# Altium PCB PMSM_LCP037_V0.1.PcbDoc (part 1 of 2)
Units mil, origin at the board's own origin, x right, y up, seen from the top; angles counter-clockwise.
Board outline 6102.36 x 5157.48 mil, 2 copper layers (Top Layer, Bottom Layer); 106 components, 56 nets, 276 pads, 861 vias.
Unrouted connection lines stored in the file: 2.
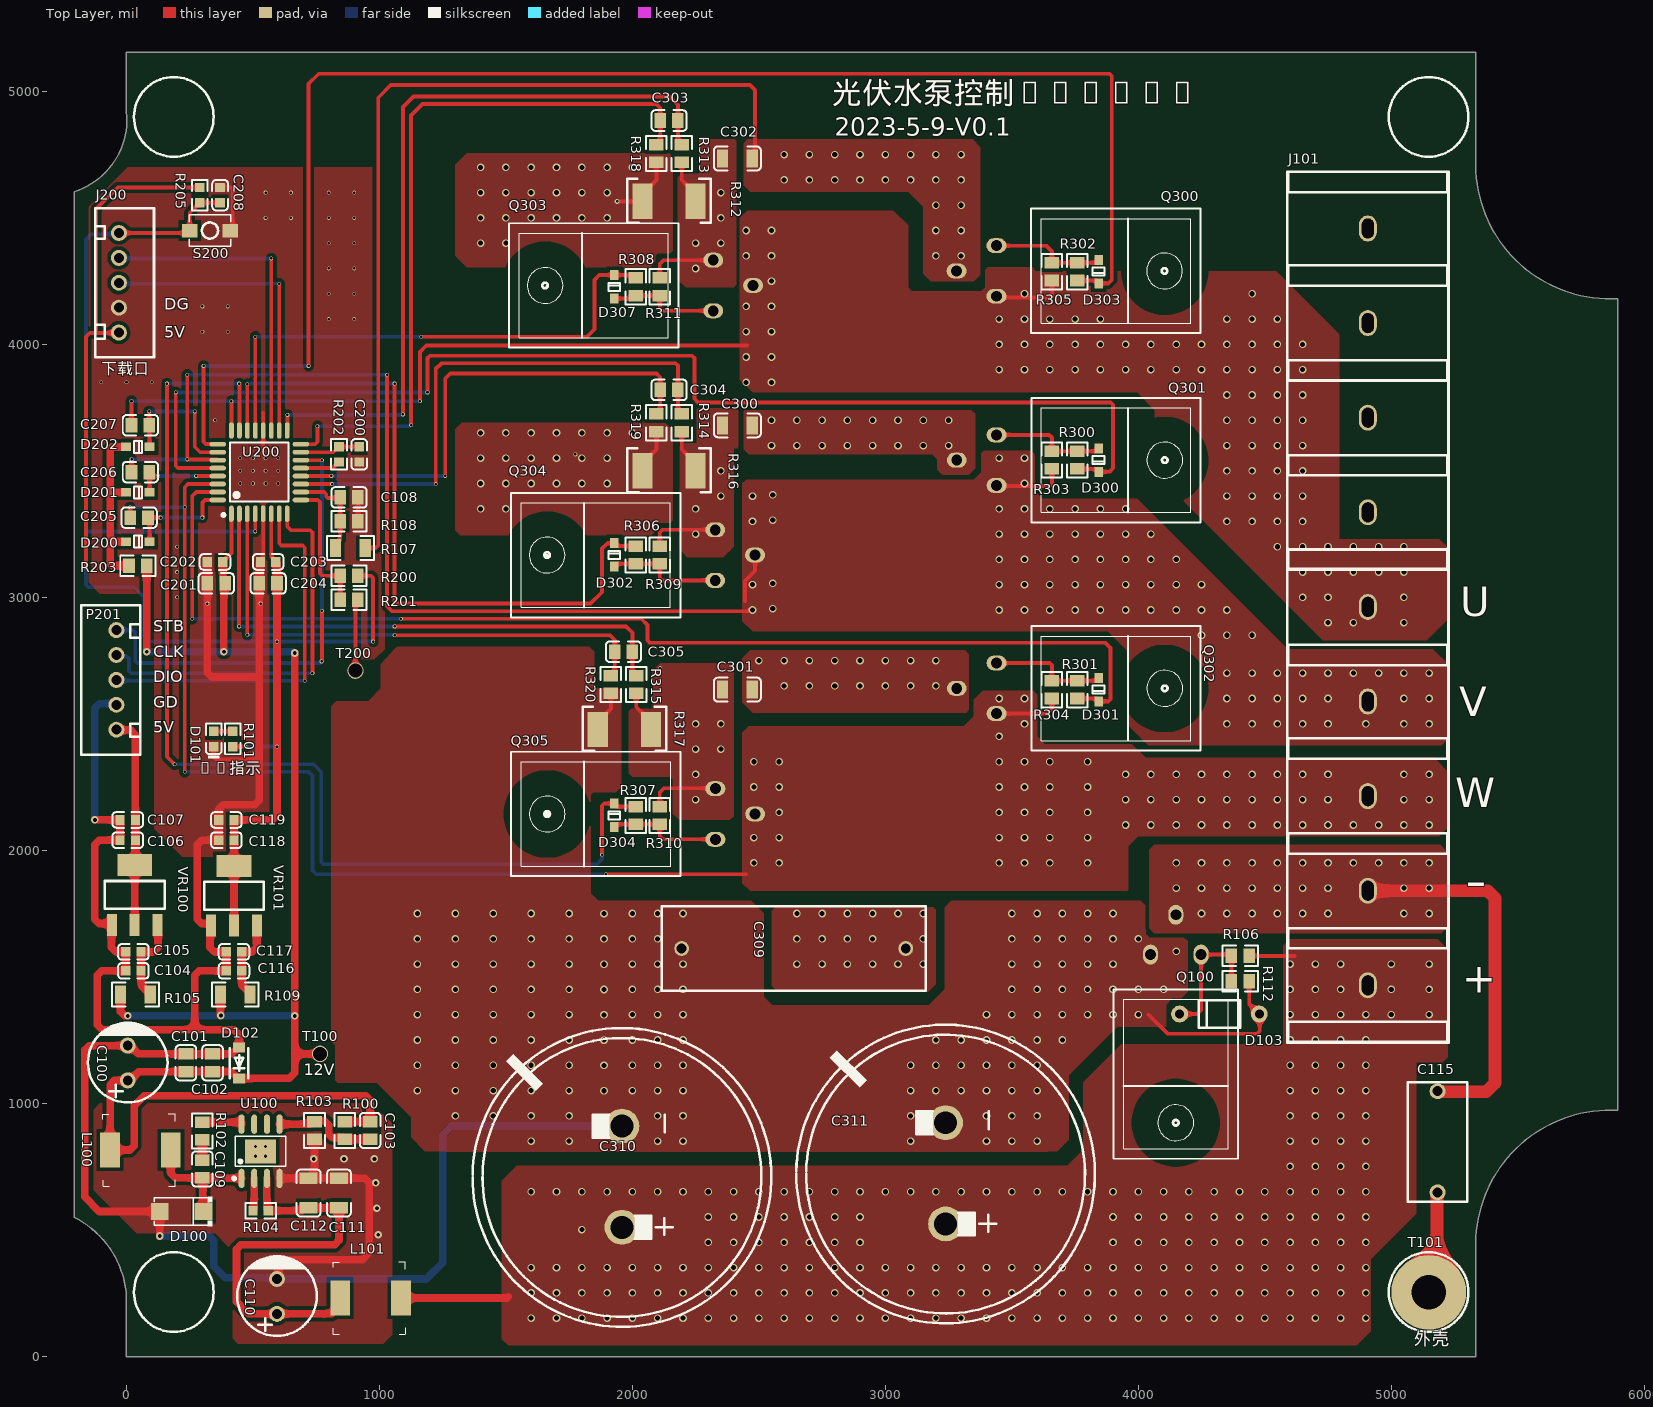
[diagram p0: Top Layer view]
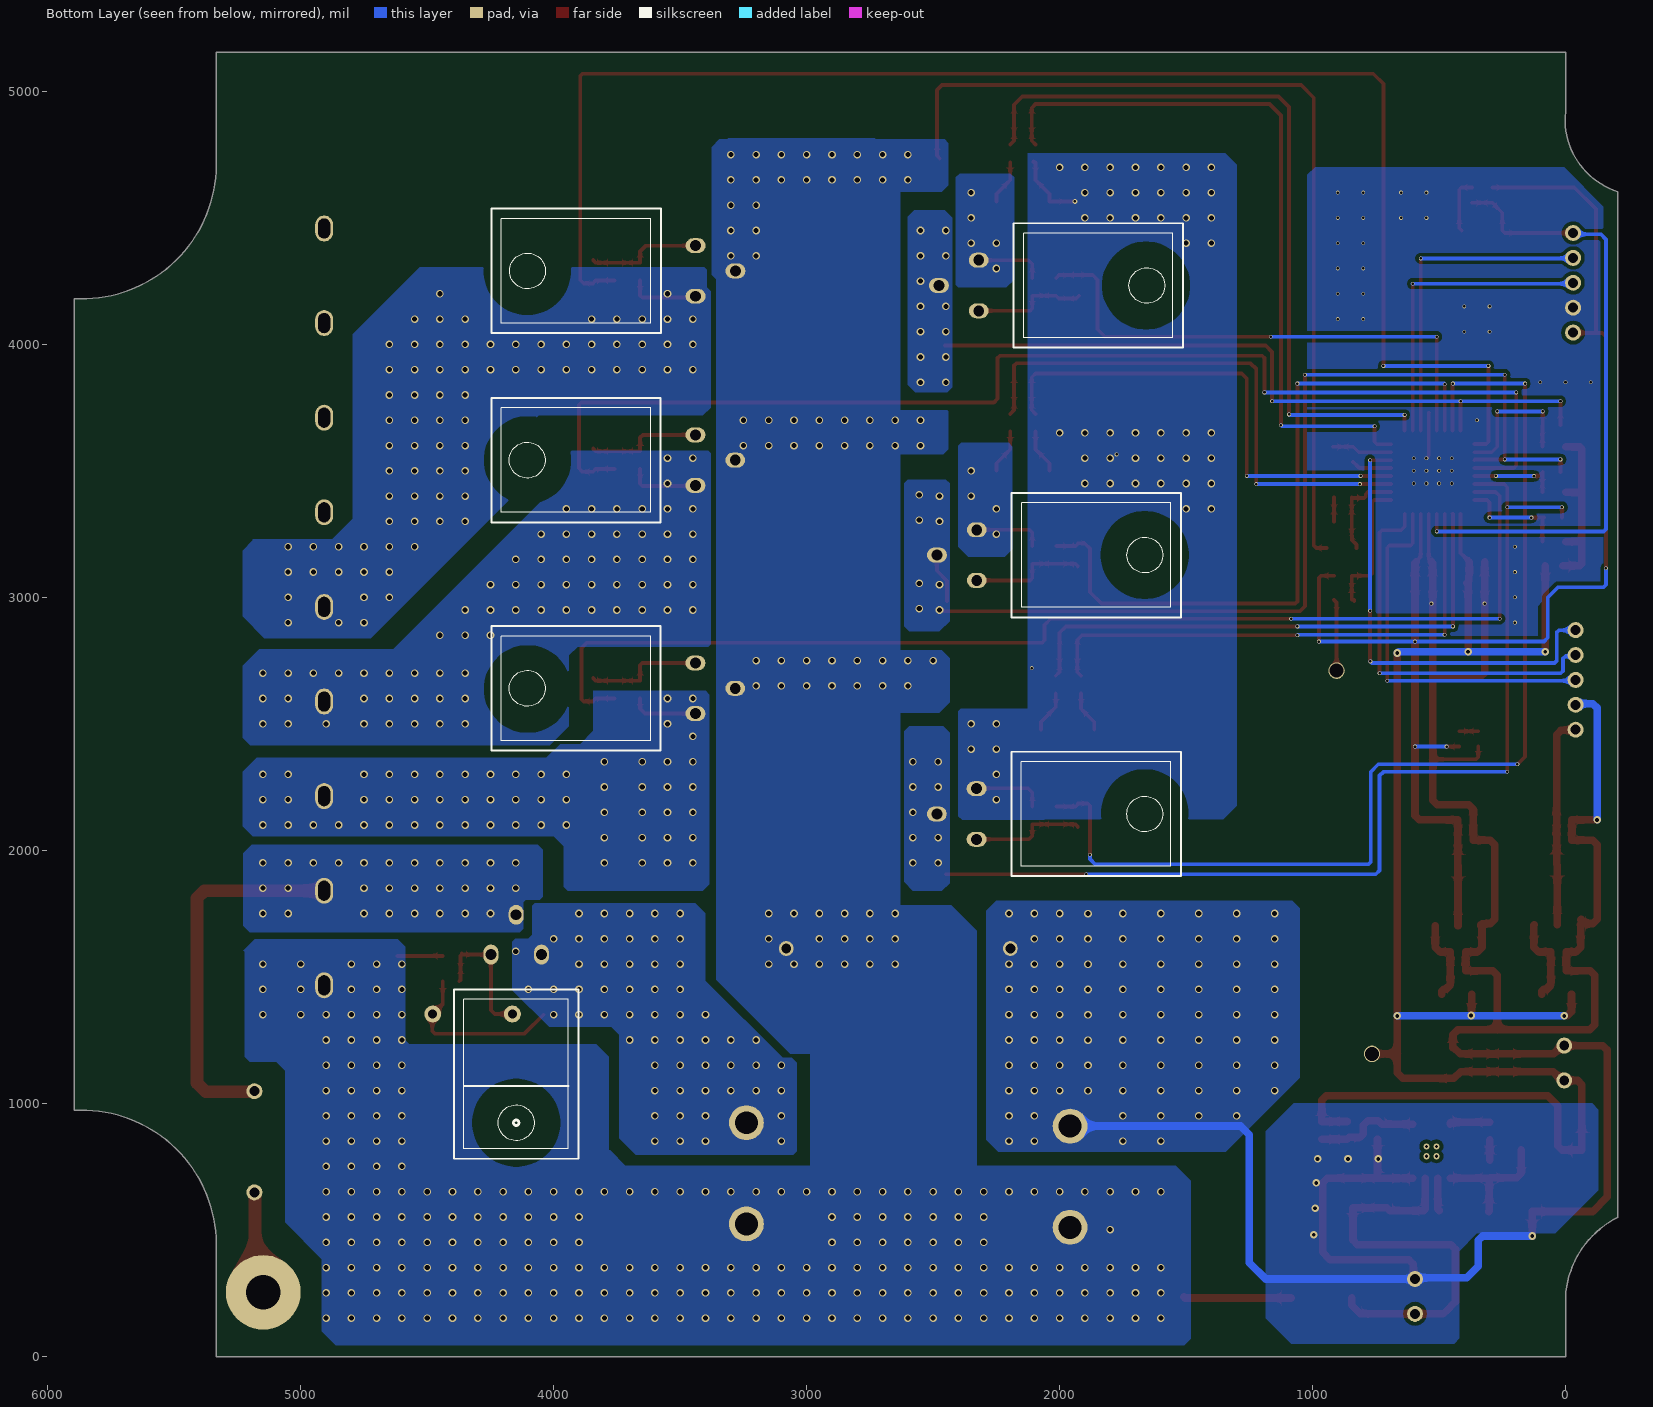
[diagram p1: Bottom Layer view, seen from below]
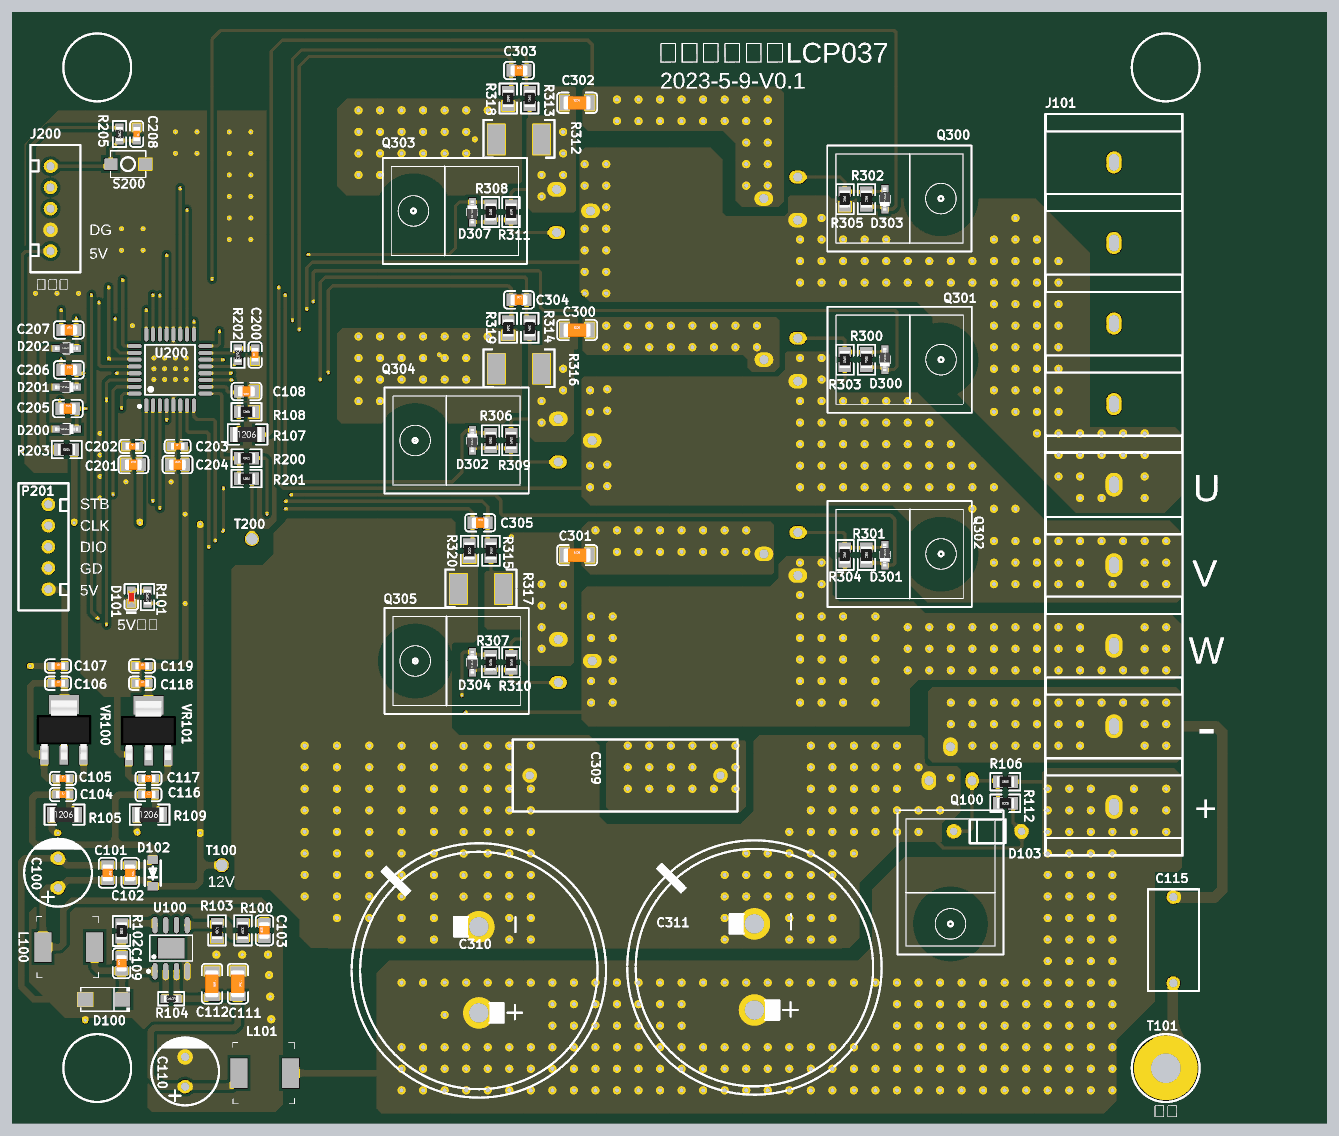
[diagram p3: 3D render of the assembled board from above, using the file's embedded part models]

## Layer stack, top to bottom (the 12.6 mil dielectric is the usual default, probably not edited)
Top Solder: solder mask 0.4, Solder Resist, Dk 3.5
Top Layer: signal copper 1.4
Dielectric 1: dielectric 12.6, FR-4, Dk 4.8
Bottom Layer: signal copper 1.4
Bottom Solder: solder mask 0.4, Solder Resist, Dk 3.5

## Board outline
0,-2.48 0,233.74 ccw(c-374.92,213) -206.69,548.7 -206.69,4603.82 ccw(c-297.17,4888.49) 0,4918.78 0,5155 5334.65,5155 5334.65,4682.56 ccw(c5866.14,4712.09) 5895.67,4180.59 5895.67,971.93 ccw(c5866.14,440.43) 5334.65,469.96 5334.65,-2.48

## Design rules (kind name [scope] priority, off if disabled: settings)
Clearance [All] p1: gap=10 ignorepadtopadclearanceinfootprint=FALSE
ComponentClearance [All] p1: gap=0 collisioncheckmode=3 verticalgap=0 showdistances=FALSE
HoleSize [All] p1: absolutevalues=TRUE maxlimit=500 minlimit=1 maxpercent=80.000 minpercent=20.000
HoleToHoleClearance [All] p1: gap=0 allowstackedmicrovias=TRUE
MinimumSolderMaskSliver [All] p1: minsoldermaskwidth=0
PlaneConnect [All] p1: planeconnectstyle=Direct reliefexpansion=20 reliefentries=4 reliefconductorwidth=10 reliefairgap=10
PolygonConnect [All] p1: connectstyle=Direct reliefconductorwidth=10 reliefentries=4 polygonreliefangle="90 Angle" airgapwidth=10
RoutingVias [All] p1: holewidth=10 width=13 viastyle="Through Hole" minholewidth=10 minwidth=13 maxholewidth=500 maxwidth=500
SilkToSilkClearance [All] p1: silktosilkclearance=0
SilkToSolderMaskClearance [IsPad] p1: minsilkscreentomaskgap=0 clearancetoexposedcopper=TRUE
SolderMaskExpansion [All] p1: expansion=4 istentingtop=FALSE
Width [All] p1: maxlimit=500 minlimit=6 preferedwidth=10
23 further rules are at their usual default settings.

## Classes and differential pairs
component class 03_Mos: C300 C301 C302 C303 C304 C305 C309 C310 C311 D300 D301 D302 D303 D304 D307 Q300 Q301 Q302 Q303 Q304 Q305 R300 R301 R302 R303 R304 R305 R306 R307 R308 R309 R310 R311 R312 R313 R314 R315 R316 R317 R318 R319 R320
component class 02_MCU: C200 C201 C202 C203 C204 C205 C206 C207 C208 D200 D201 D202 J200 P201 R200 R201 R202 R203 R205 S200 T200 U200
component class 01_Power: C100 C101 C102 C103 C104 C105 C106 C107 C108 C109 C110 C111 C112 C115 C116 C117 C118 C119 D100 D101 D102 D103 J101 L100 L101 Q100 R100 R101 R102 R103 R104 R105 R106 R107 R108 R109 R112 T100 T101 U100 VR100 VR101

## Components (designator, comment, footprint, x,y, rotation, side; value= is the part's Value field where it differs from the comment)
C100 "470uF/25V" 47UF/100V 5,1090 r90 top
C101 "22uF (226) 20% 25V" 0805_C 235,1160 r270 top
C102 "100nF(104) 10% 50V" 0805_C 340,1160 r270 top
C103 "47pF (470) 5% 50V" 0805_C 963.31,892.52 r90 top
C104 "100nF (104) 10% 50V" 0603_C 27.48,1523.31 r0 top
C105 "10uF (106) 10% 10V" 0603_C 27.48,1598.31 r0 top
C106 "100nF (104) 10% 50V" 0603_C 5,2040 r0 top
C107 "10uF (106) 10% 10V" 0603_C 5,2120 r0 top
C108 "100nF(104) 10% 50V" 0805_C 880,3395 r180 top
C109 "100nF(104) 10% 50V" 0805_C 300,740 r90 top
C110 "47uF/100V" 47UF/100V 595,167.2 r90 top
C111 "2.2uF (225) 10% 50V" 1206_C 840,645 r270 top
C112 "100nF (104) 10% 50V" 1206_C 720,645 r270 top
C115 "2.2nF (222) 10% 50V" "X1/Y1 500V" 5183.31,1047.52 r270 top
C116 "100nF (104) 10% 50V" 0603_C 425,1523.31 r0 top
C117 "10uF (106) 10% 10V" 0603_C 425,1598.31 r0 top
C118 "100nF (104) 10% 50V" 0603_C 395,2040 r0 top
C119 "10uF (106) 10% 10V" 0603_C 395,2120 r0 top
C200 "1uF (105) 10% 50V" 0603_C 920,3565 r90 top
C201 "10uF (106) 10% 25V" 0805_C 354.96,3055 r0 top
C202 "100nF (104) 10% 50V" 0603_C 350,3140 r0 top
C203 "100nF (104) 10% 50V" 0603_C 560,3140 r0 top
C204 "10uF (106) 10% 25V" 0805_C 560,3055 r0 top
C205 "10uF (106) 10% 25V" 0805_C 50,3315 r0 top
C206 "10uF (106) 10% 25V" 0805_C 54.88,3495 r0 top
C207 "10uF (106) 10% 25V" 0805_C 54.88,3680 r0 top
C208 "100nF (104) 10% 50V" 0603_C 370,4590 r270 top
C300 "100nF (104) 10% 100V" 1206_C 2415,3680 r0 top
C301 "100nF (104) 10% 100V" 1206_C 2415,2635 r0 top
C302 "100nF (104) 10% 100V" 1206_C 2415,4735 r0 top
C303 "100pF (101) 5% 50V" 0805_C 2145,4885 r0 top
C304 "100pF (101) 5% 50V" 0805_C 2145,3820 r0 top
C305 "100pF (101) 5% 50V" 0805_C 1965,2785 r0 top
C309 "X2 1UF/310V" "X2 1UF 310V" 2194.88,1611.69 r0 top
C310 "1000uF/250V" 1000uf/250V 1958.66,509.33 r90 top
C311 "1000uF/250V" 1000uf/250V 3238.19,522.72 r90 top
D100 "SS310" SS310 215,570 r180 top
D101 "绿灯 0603" 0603_LED_S1 345,2440 r90 top
D102 "SMF12A" "SMF12A - duplicate" 445,1097.95 r90 top
D103 "1N4746A" 1N4746A 4301.77,1252.64 r180 top
D200 "1N4148WS T4" SOD-323 45,3220 r180 top
D201 "1N4148WS T4" SOD-323 44.88,3415 r180 top
D202 "1N4148WS T4" SOD-323 44.88,3595 r180 top
D300 "1N4148WS T4" SOD-323 3843.31,3542.52 r90 top
D301 "1N4148WS T4" SOD-323 3843.31,2635 r90 top
D302 "1N4148WS T4" SOD-323 1928.31,3167.52 r270 top
D303 "1N4148WS T4" SOD-323 3843.31,4287.52 r90 top
D304 "1N4148WS T4" SOD-323 1928.31,2137.52 r270 top
D307 "1N4148WS T4" SOD-323 1928.31,4227.52 r270 top
J101 "CON9" "CON9 9.5mm" 4907.48,1466.02 r90 top locked
J200 "SWD-KF2510-5P" XH2.54-5P -30,4046.58 r90 top
L100 "47uH/0650" 0650_47UH 45,815 r180 top
L101 "47uH/0650" 0650_47UH 955,230 r180 top
P201 "Header 5" XH2.54-5P -40,2870.28 r270 top
Q100 "IRFB4127PBF" IRFB4127#1 4148.31,1745 r180 top locked
Q300 "IRFB4127PBF" IRFB4127#2 3439.02,4390.24 r270 top locked
Q301 "IRFB4127PBF" IRFB4127#2 3439.8,3642.2 r270 top locked
Q302 "IRFB4127PBF" IRFB4127#2 3439.8,2740.24 r270 top locked
Q303 "IRFB4127PBF" IRFB4127#2 2319.72,4132.76 r90 top locked
Q304 "IRFB4127PBF" IRFB4127#2 2327.6,3067.01 r90 top locked
Q305 "IRFB4127PBF" IRFB4127#2 2327.99,2043.39 r90 top locked
R100 "330KΩ (3303) ±1%" 0805_R 863.31,892.52 r90 top
R101 "10KΩ (1002) ±1%" 0603_R 420,2440 r270 top
R102 "22Ω (22R0) ±1%" 0805_R 300,890 r90 top
R103 "23.7KΩ" 0805_R 743.31,892.52 r90 top
R104 "30mΩ ±1%" 0603_R 530,575 r0 top
R105 "200Ω (2000) ±1%" 1206_R 35,1430 r0 top
R106 "20KΩ (2002) ±1%" 0805_R 4403.31,1582.52 r0 top
R107 "24KΩ (2402) ±1%" 1206_R 885,3195 r0 top
R108 "1KΩ (1001) ±1%" 0805_R 880,3300 r180 top
R109 "200Ω (2000) ±1%" 1206_R 430,1430 r0 top
R112 "10KΩ (1002) ±1%" 0805_R 4403.31,1482.52 r180 top
R200 "1KΩ (1001) ±1%" 0805_R 880,3085 r0 top
R201 "1KΩ (1001) ±1%" 0805_R 880,2990 r180 top
R202 "10KΩ (1002) ±1%" 0603_R 840,3565 r270 top
R203 "1KΩ (1001) ±1%" 0805_R 45,3125 r180 top
R205 "10KΩ (1002) ±1%" 0603_R 290,4590 r90 top
R300 "51Ω (51R0) ±1%" 0805_R 3758.31,3542.56 r90 top
R301 "51Ω (51R0) ±1%" 0805_R 3758.31,2635 r90 top
R302 "51Ω (51R0) ±1%" 0805_R 3758.31,4287.52 r90 top
R303 "100KΩ (1003) ±1%" 0805_R 3658.31,3542.52 r90 top
R304 "100KΩ (1003) ±1%" 0805_R 3658.31,2635 r90 top
R305 "100KΩ (1003) ±1%" 0805_R 3658.31,4287.52 r90 top
R306 "51Ω (51R0) ±1%" 0805_R 2013.31,3167.52 r270 top
R307 "51Ω (51R0) ±1%" 0805_R 2013.31,2137.52 r270 top
R308 "51Ω (51R0) ±1%" 0805_R 2013.31,4227.52 r270 top
R309 "100KΩ (1003) ±1%" 0805_R 2108.31,3167.52 r270 top
R310 "100KΩ (1003) ±1%" 0805_R 2108.31,2137.52 r270 top
R311 "100KΩ (1003) ±1%" 0805_R 2108.31,4227.52 r270 top
R312 "10mR 2512" R2512 2170,4525 r0 top
R313 "68Ω (68R0) ±1%" 0805_R 2195,4755 r270 top
R314 "68Ω (68R0) ±1%" 0805_R 2195,3690 r270 top
R315 "68Ω (68R0) ±1%" 0805_R 2015,2655 r270 top
R316 "10mR 2512" R2512 2170,3460 r0 top
R317 "10mR 2512" R2512 1993.31,2437.52 r0 top
R318 "68Ω (68R0) ±1%" 0805_R 2095,4755 r270 top
R319 "68Ω (68R0) ±1%" 0805_R 2095,3690 r270 top
R320 "68Ω (68R0) ±1%" 0805_R 1915,2655 r270 top
S200 "KEY" 按键3*4 249.76,4450 r0 top
T100 "Test" Testpoint 765,1195 r90 top
T101 "Test" 接地螺丝孔 5148.31,252.52 r0 top
T200 "Test" Testpoint 905,2710 r90 top
U100 "TX4139" ESOP8 455,702.89 r0 top
U200 "LCP037BK32ET8" LQFP32 425,3395 r270 top
VR100 "AMS1117-5.0" SOT-223 32.48,1823.31 r270 top
VR101 "AMS1117-5.0" SOT-223 425,1820 r270 top

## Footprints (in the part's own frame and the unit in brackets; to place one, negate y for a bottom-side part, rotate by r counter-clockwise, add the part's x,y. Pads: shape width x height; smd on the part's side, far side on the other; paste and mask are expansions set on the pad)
1N4746A [mm]
  round 1.7 hole 0.9 paste+0 mask+0.051: 1(-4.484,-2.537) 2(3.516,-2.537)
  silkscreen extent -2.58,-3.94 1.62,-1.14
47UF/100V [mm] "8*14"
  round 1.6 hole 1: 1(0,0) 2(3.5,0)
  silkscreen extent -2.21,-4 5.79,4
0603_C [mm]
  rect 0.93x0.98 smd: 1(-0.77,0) 2(0.77,0)
  silkscreen extent -1.53,-0.79 1.54,0.79, body extent -0.8,-0.4 0.8,0.4, height 0.3
0603_LED_S1 [mm]
  rect 0.93x0.98 smd: A(0.77,0) K(-0.77,0)
  silkscreen extent -1.98,-0.79 1.54,0.79, body extent -0.8,-0.4 0.8,0.4, height 0.6
0603_R [mm]
  rect 0.93x0.98 smd: 1(-0.77,0) 2(0.77,0)
  silkscreen extent -1.53,-0.79 1.54,0.79, body extent -0.85,-0.4 0.85,0.4, height 0.56
0650_47UH [mm]
  rect 2x3.5 smd: 1(-3.302,0) 2(2.794,0)
  silkscreen extent -3.76,-3.62 3.52,3.62
0805_C [mm]
  rect 1.16x1.47 smd: 1(-0.89,0) 2(0.89,0)
  silkscreen extent -1.77,-1.04 1.77,1.04, body extent -1,-0.62 1,0.63, height 0.77
0805_R [mm]
  rect 1.16x1.47 smd: 1(-0.89,0) 2(0.89,0)
  silkscreen extent -1.77,-1.04 1.77,1.03, body extent -1,-0.62 1,0.63, height 0.49
1000uf/250V [mm]
  round 3.5 hole 2.3: 1(0,0) 2(10.16,0)
  silkscreen extent -9.99,-15 20.01,15
1206_C [mm]
  rect 1.13x1.8 smd: 1(-1.49,0) 2(1.49,0)
  silkscreen extent -2.36,-1.2 2.35,1.2, body extent -1.6,-0.81 1.6,0.79, height 1
1206_R [mm]
  rect 1.13x1.8 smd: 1(-1.49,0) 2(1.49,0)
  silkscreen extent -2.36,-1.2 2.35,1.2, body extent -1.7,-0.86 1.65,0.87, height 0.85
"CON9 9.5mm" [mm]
  oval 2.6x1.8 hole 1.2 slot 2 at 0 deg: 1(0,0) 2(9.5,0) 3(19,0) 4(28.5,0) 5(38,0) 6(47.5,0) 7(57,0) 8(66.5,0) 9(76,0)
  silkscreen extent -5.75,-8.1 81.69,8.1
ESOP8 [mm]
  oval 0.602x1.941 smd: 1(0,0) 2(1.27,0) 3(2.54,0) 4(3.81,0) 5(3.81,5.441) 6(2.54,5.441) 7(1.27,5.441) 8(0,5.441)
  rect 3.098x2.41 smd: 9(1.905,2.72)
  silkscreen extent -0.9,-0.15 4.43,4.24
IRFB4127#1 [mm]
  oval 1.5x2 hole 1.1: 1(-2.54,4) 2(0,0) 3(2.54,4)
  silkscreen extent -6.25,7.5 6.25,24.5
IRFB4127#2 [mm] "TO-220AB"
  oval 1.5x2 hole 1.1: 1(0,0) 2(2.54,-4) 3(5.08,0)
  round 0 on Bottom Overlay: ""(2.54,16.885)
  silkscreen extent -3.71,3.5 8.79,20.5
LQFP32 [mm]
  oval 1.65x0.48 smd: 1(1.635,-0.26) 2(1.635,0.54) 3(1.635,1.34) 4(1.635,2.14) 5(1.635,2.94) 6(1.635,3.74) 7(1.635,4.54) 8(1.635,5.34) 17(-6.715,5.34) 18(-6.715,4.54) 19(-6.715,3.74) 20(-6.715,2.94) 21(-6.715,2.14) 22(-6.715,1.34) 23(-6.715,0.54) 24(-6.715,-0.26)
  oval 0.48x1.65 smd: 9(0.26,6.715) 10(-0.54,6.715) 11(-1.34,6.715) 12(-2.14,6.715) 13(-2.94,6.715) 14(-3.74,6.715) 15(-4.54,6.715) 16(-5.34,6.715) 25(-5.34,-1.635) 26(-4.54,-1.635) 27(-3.74,-1.635) 28(-2.94,-1.635) 29(-2.14,-1.635) 30(-1.34,-1.635) 31(-0.54,-1.635) 32(0.26,-1.635)
  silkscreen extent -5.49,-1.21 1.91,5.49
R2512 [mil]
  rect 80x140 smd: 1(-130,40) 2(80,40)
  silkscreen extent -190,-45 140,130
"SMF12A - duplicate" [mm] "SOD123F"
  rect 1x1.2 smd: 1(0,0) 2(3.1,0)
  silkscreen extent 0.03,-0.93 3.04,0.95
SOD-323 [mm]
  rect 1x0.83 smd: 1(1.18,0) 2(-1.18,0)
  silkscreen extent -0.4,-0.6 0.4,0.6, body extent -1.35,-0.62 1.35,0.63, height 1.1
SOT-223 [mm]
  rect 2.2x1 smd: 1(3,-2.3) 2(3,0) 3(3,2.3)
  rect 2.2x3.5 smd: 2(-3,0)
  silkscreen extent -1.4,-3 1.4,3, body extent -3.49,-3.24 3.49,3.24, height 1.64
SS310 [mm]
  rect 1.8x1.7 smd paste+0 mask+0.051: 1(-2.26,-0.047) 2(2.125,-0.047)
  silkscreen extent -3.17,-1.52 2.66,1.43
Testpoint [mil]
  round 65 hole 55: 1(0,0)
"X1/Y1 500V" [mm]
  round 1.6 hole 1: 1(0,0) 2(10.16,0)
  silkscreen extent -0.92,-3 11.08,3
"X2 1UF 310V" [mm]
  round 1.5 hole 1: 1(0,0) 2(22.5,0)
  silkscreen extent -2,-4.25 24.5,4.25
XH2.54-5P [mm]
  round 1.6 hole 1 paste+0 mask+0.05: 1(0,0) 2(2.5,0) 3(5,0) 4(7.5,0) 5(10,0)
  silkscreen extent -2.5,-3.53 12.5,2.38
按键3*4 [mm]
  rect 1.53x1.36 smd: 1(0,0) 2(4.07,0)
  silkscreen extent -0.04,-1.58 4.11,1.58
接地螺丝孔 [mm]
  round 7.5 hole 3.5: 6(0,0)

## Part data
C100 C110: library part CapSMT220u_16V
C101: library part "0805 22uF (226) 20% 25V", "贴片电容", Package=0805, SuppliersPartNumber=C45783
C102 C108 C109: library part "0805 100nF(104) 10% 50V", "贴片电容", Package=0805, SuppliersPartNumber=C49678
C103: library part "0805 47pF (470) 5% 50V", "贴片电容", Package=0805, SuppliersPartNumber=C14857
C104 C106 C116 C118 C202 C203 C208: library part "0603 100nF (104) 10% 50V", "贴片电容", Package=0603, SuppliersPartNumber=C14663
C105 C107 C117 C119: library part "0603 10uF (106) 10% 10V", "贴片电容", Package=0603, SuppliersPartNumber=C19702
C111: library part "1206 2.2uF (225) 10% 50V", "贴片电容", Package=1206, SuppliersPartNumber=C12656
C112 C300 C301 C302 C309: library part "1206 100nF (104) 10% 50V", "贴片电容", Package=1206, SuppliersPartNumber=C24497
C115: library part "0603 2.2nF (222) 10% 50V", "贴片电容", Package=0603, SuppliersPartNumber=C1604
C200: library part "0603 1uF (105) 10% 50V", "贴片电容", Package=0603, SuppliersPartNumber=C15849
C201 C204 C205 C206 C207: library part "0805 10uF (106) 10% 25V", "贴片电容", Package=0805, SuppliersPartNumber=C15850
C303 C304 C305: library part "0805 100pF (101) 5% 50V", "贴片电容", Package=0805, SuppliersPartNumber=C1790
C310 C311: library part CAP2, "电解电容"
D101: library part "0603 绿灯", "发光二极管", Package=0603, SuppliersPartNumber=C72043
D200 D201 D202 D300 D301 D302 D303 D304 D307: library part "SOD-323 1N4148WS T4", "二极管", Package=SOD-323, SuppliersPartNumber=C2128
J200: library part ST-LINK-SWD
L100 L101: library part Inductor
P201: "Header, 5-Pin"
R100: library part "0805 330KΩ (3303) 1%", "贴片电阻", Package=0805, SuppliersPartNumber=C17629
R101 R202 R205: library part "0603 10KΩ (1002) 1%", "贴片电阻", Package=0603, SuppliersPartNumber=C25804
R102 R103: library part "0805 22Ω (22R0) 1%", "贴片电阻", Package=0805, SuppliersPartNumber=C17561
R104: library part "0603 100KΩ (1003) 1%", "贴片电阻", Package=0603, SuppliersPartNumber=C25803
R105 R109: library part "1206 300Ω (3000) 1%", "贴片电阻", Package=1206, SuppliersPartNumber=C17887
R106: library part "0805 20KΩ (2002) 1%", "贴片电阻", Package=0805, SuppliersPartNumber=C4328
R107: library part "1206 0Ω (0R0) 1%", "贴片电阻", Package=1206, SuppliersPartNumber=C17888
R108 R200 R201 R203: library part "0805 1KΩ (1001) 1%", "贴片电阻", Package=0805, SuppliersPartNumber=C17513
R112: library part "0805 10KΩ (1002) 1%", "贴片电阻", Package=0805, SuppliersPartNumber=C17414
R300 R301 R302 R306 R307 R308: library part "0805 51Ω (51R0) 1%", "贴片电阻", Package=0805, SuppliersPartNumber=C17738
R303 R304 R305 R309 R310 R311: library part "0805 100KΩ (1003) 1%", "贴片电阻", Package=0805, SuppliersPartNumber=C17407
R312 R316 R317: library part Res10K
R313 R314 R315 R318 R319 R320: library part "0805 68Ω (68R0) 1%", "贴片电阻", Package=0805, SuppliersPartNumber=C17802
T100 T101 T200: library part TestPad
U200: library part LCP037BT32EU8
VR100 VR101: library part "SOT-223 AMS1117-5.0", "低压差线性稳压(LDO)", Package=SOT-223, SuppliersPartNumber=C6187

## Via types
v1: diameter 30, hole 20, Top Layer to Bottom Layer, 742 vias
v2: diameter 15, hole 10, Top Layer to Bottom Layer, 100 vias
v3: diameter 30, hole 15, Top Layer to Bottom Layer, 14 vias
v4: diameter 24, hole 12, Top Layer to Bottom Layer, 4 vias
v5: diameter 20, hole 10, Top Layer to Bottom Layer, 1 vias

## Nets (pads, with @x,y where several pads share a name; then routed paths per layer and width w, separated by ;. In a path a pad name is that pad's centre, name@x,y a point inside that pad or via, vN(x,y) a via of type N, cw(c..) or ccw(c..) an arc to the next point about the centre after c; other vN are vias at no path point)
5V: C106.2 C107.2 P201.5 VR100.2 | length 836.7
  Top Layer w30: P201.5@-40,2476.57 -38.43,2475 17.74,2475 35.32,2457.43 35.32,2342.43 C107.2@35.32,2120 C106.2@35.32,2040 35.32,1944.25 VR100.2@32.48,1941.42 VR100.2@32.48,1705.2
5VDD: C118.2 C119.2 C203.2 C204.2 J200.1 R101.2 R200.2 R205.2 U200.6 VR101.2 | length 5663.2
  Top Layer w15: v2(-160,3115) -160,4030 -145,4045 -123.5,4045 ; J200.1@-30,4046.58 -31.57,4045 -123.5,4045 ; R205.2@290,4620.32 -34.68,4620.32 -120,4535 -120,4048.5 -123.5,4045 ; R101.2@420,2409.68 469.68,2409.68 v2(470,2410) ; U200.6@572.24,3330.63 572.24,3159.06 590.32,3140.98 C203.2@590.32,3140 ; R200.2@915.04,3085 966.21,3085 975,3076.21 v2(975,2825)
  Top Layer w30: VR101.2@425,1701.89 VR101.2@425,1938.11 425.32,1938.43 C118.2@425.32,2040 C119.2@425.32,2120 577.47,2120 595.04,2137.57 595.04,2812.5 C204.2@595.04,3055 595.04,3134.29 590.32,3139.02 C203.2@590.32,3140
  Bottom Layer w15: v2(-160,3115) -160,3050 -150,3040 30,3040 70.11,2999.89 70.11,2840 85.11,2825 v2(975,2825) ; v2(470,2410) v2(595,2410)
  other v2: 595,2825
12VDD: C100.1 C101.2 C102.2 C103.2 C201.2 C202.2 D102.1 L100.2 R100.2 R105.1 R109.1 R203.1 T100.1 U200.1 | length 6517.5
  Top Layer w15: C202.2@380.32,3140 380.32,3140.98 414.76,3175.43 U200.1@414.76,3330.63
  Top Layer w30: R105.1@-23.66,1430 -23.66,1362.57 v3@-6.09,1345 ; v3(80,2785) v3(80,2785) R203.1@80.04,3125 ; v3@371.34,1348.66 R109.1@371.34,1430 ; C202.2@380.32,3140 380.32,3086.46 382.17,3084.61 382.17,3062.83 C201.2@390,3055 385,3050 v3(385,2785) ; v3(665,2780) v3(665,1345) 665,1195 ; T100.1@765,1195 665,1195 ; R100.2@863.31,927.56 C103.2@963.31,927.56 963.31,1011.69 945,1030 70,1030 30,990 30,832.57 12.43,815 L100.2@-65,815 -65,1072.43 -47.43,1090 C100.1@5,1090 13.93,1090 48.89,1124.96 C101.2@235,1124.96 C102.2@340,1124.96 414.06,1124.96 441.06,1097.95 642.95,1097.95 665,1120 665,1195
  Bottom Layer w30: v3(5,1345) v3(665,1345) ; v3(80,2785) v3(385,2785) 660,2785 v3(665,2780)
  other v3: 373.17,1346.83
DGND: C100.2 C101.1 C102.1 C104.1 C105.1 C106.1 C107.1 C108.1 C110.2 C111.1 C112.1 C116.1 C117.1 C118.1 C119.1 C200.1 C201.1 C202.1 C203.1 C204.1 C208.1 C309.1 C310.2 C311.2 D100.2 D101.K D102.2 D103.1 J200.2 P201.4 Q100.3 R103.1 R108.1 R112.1 R317.1 R320.2 S200.2 U100.4 U200.5 U200.20 VR100.1 VR101.1 | length 12520.4
  Top Layer w15: C202.1@319.68,3140 319.68,3055.24 319.8,3055.12 C201.1@319.92,3055 ; D101.K@345,2409.69 345,2368.79 353.79,2360 524.96,2360 ; C208.1@370,4620.32 411.21,4620.32 420,4611.53 420,4460 S200.2@410,4450 ; 540,3730 540.75,3729.25 U200.20@540.75,3659.37 540.75,3559.25 v2(550,3550) ; C203.1@540.75,3152.05 U200.5@540.75,3330.63 ; R108.1@915.04,3300 C108.1@915.04,3395 ; R317.1@1863.31,2477.52 1863.31,2507.52 1915,2559.21 R320.2@1915,2619.96 ; 4040,1350 4115,1275 4470,1275 4480,1285 4480,1350.83 D103.1@4478.31,1352.52 4438.35,1392.48 R112.1@4438.35,1482.52
  Top Layer w30: v3(-125,2120) C107.1@-25.32,2120 C106.1@-25.32,2040 -107.43,2040 -125,2022.43 -125,1727.57 -107.43,1710 -62.76,1710 -62.76,1709.88 VR100.1@-58.07,1705.2 ; VR100.1@-62.76,1727.57 VR100.1@-60,1724.82 ; VR100.1@-60,1707.24 -60,1615.88 -42.43,1598.31 C105.1@-2.83,1598.31 C104.1@-2.83,1523.31 -97.43,1523.31 -115,1505.73 -115,1310 -95,1290 270,1290 ; v3(131.56,475) 131.35,475.2 D100.2@131.35,571.83 -106.83,571.83 -165,630 -165,1210.23 -147.43,1227.8 C100.2@5,1227.8 13.93,1227.8 46.69,1195.04 C101.1@235,1195.04 C102.1@340,1195.04 416.1,1195.04 441.06,1220 D102.2@445,1220 445,1270 425,1290 270,1290 ; C202.1@319.68,3140 319.8,3139.88 C201.1@319.8,3055.12 ; C201.1@319.92,3055 319.92,2702.57 337.49,2685 519.96,2685 524.96,2690 ; C203.1@529.68,3140 529.68,3139.02 524.96,3134.29 C204.1@524.96,3055 524.96,2690 ; C110.2@595,305 601.31,311.31 601.31,364.2 618.89,381.77 931.77,381.77 960,410 960,686.09 942.43,703.66 C111.1@840,703.66 C112.1@733.19,703.66 ; U100.4@605,702.89 605.38,703.28 719.62,703.28 C112.1@720,703.66 C112.1@733.19,703.66 ; R103.1@743.31,857.48 743.31,713.78 C112.1@733.19,703.66 ; 270,1290 270,1505.73 287.57,1523.31 C116.1@394.68,1523.31 C117.1@394.68,1598.31 347.57,1598.31 330,1615.88 330,1697.44 VR101.1@334.45,1701.89 334.45,1705.31 329.76,1710 297.57,1710 280,1727.57 280,2022.43 297.57,2040 C118.1@364.68,2040 C119.1@364.68,2120 364.68,2162.43 382.26,2180 507.39,2180 524.96,2197.57 524.96,2360 524.96,2690
  Bottom Layer w30: v3(-125,2120) -125,2562.43 -107.43,2580 -45,2580 P201.4@-40,2575 ; v3(131.56,475) 327.43,475 345,457.43 345,355 390,310 590,310 C110.2@595,305 1185,305 1250,370 1250,875 1285,910 1957.99,910 C310.2@1958.66,909.33
  other v1: 1600,850 1750,850 2100,850 2200,850 3100,850 3400,850 3500,850 3600,850 1300,950 1450,950 1600,950 1750,950 2100,950 2200,950 3100,950 3400,950 3500,950 3600,950 1887.83,1049.36 1150,1050 1300,1050 1450,1050 1600,1050 1750,1050 2000,1050 2100,1050 2200,1050 3100,1050 3200,1050 3300,1050 3400,1050 3500,1050 3600,1050 1887.83,1149.36 1150,1150 1300,1150 1450,1150 1600,1150 1750,1150 2000,1150 2100,1150 2200,1150 3100,1150 3200,1150 3300,1150 3400,1150 3500,1150 3600,1150 1887.83,1249.36 1150,1250 1300,1250 1450,1250 1600,1250 1750,1250 2000,1250 2100,1250 2200,1250 3200,1250 3300,1250 3400,1250 3500,1250 3600,1250 3700,1250 1887.83,1349.36 1150,1350 1300,1350 1450,1350 1600,1350 1750,1350 2000,1350 2100,1350 2200,1350 3400,1350 3500,1350 3600,1350 3700,1350 3800,1350 3900,1350 4000,1350 1887.83,1449.36 1150,1450 1300,1450 1450,1450 1600,1450 1750,1450 2000,1450 2100,1450 2200,1450 3500,1450 3600,1450 3700,1450 3800,1450 3900,1450 4000,1450 4100,1450 1887.83,1549.36 1150,1550 1300,1550 1450,1550 1600,1550 1750,1550 2000,1550 2100,1550 2200,1550 3500,1550 3600,1550 3700,1550 3800,1550 3900,1550 4150,1600 1887.83,1649.36 1150,1650 1300,1650 1450,1650 1600,1650 1750,1650 2000,1650 2100,1650 3500,1650 3600,1650 3700,1650 3800,1650 3900,1650 4000,1650 1887.83,1749.36 1150,1750 1300,1750 1450,1750 1600,1750 1750,1750 2000,1750 2100,1750 2200,1750 3500,1750 3600,1750 3700,1750 3800,1750 3900,1750
  other v2: 200,2900 320,2975 530,2975 200,3000 200,3100 200,3200 450,3450 500,3450 550,3450 600,3450 450,3500 500,3500 550,3500 600,3500 450,3550 500,3550 600,3550 350,3700 -100,3850 0,3850 100,3850 300,4050 400,4050 800,4100 900,4100 300,4150 400,4150 800,4200 900,4200 800,4300 900,4300 800,4400 900,4400 550,4500 650,4500 800,4500 900,4500 550,4600 650,4600 800,4600 900,4600
  other v3: 995,480 990,585 985,685 740,780 860,780 980,780
FG: R200.1 R201.2 U200.9 | length 545.1
  Top Layer w15: U200.9@689.37,3384.76 756.21,3384.76 765,3375.98 765,3093.79 773.79,3085 R200.1@844.96,3085 R201.2@844.96,2990 ; R201.2@834.96,2985 R201.2@834.96,2990
GND: C115.1 J101.2 Q100.2 | length 1487.6
  Top Layer w50: J101.2@4907.48,1840.04 5380.71,1840.04 5410,1810.75 5410,1080 5375,1045 5289.34,1045 ; C115.1@5183.31,1047.52 5185.79,1045.03 5289.31,1045.03
  other v1: 4250,1750 4350,1750 4450,1750 4550,1750 4650,1750 4750,1750 5050,1750 5150,1750 4150,1850 4250,1850 4350,1850 4450,1850 4550,1850 4650,1850 4750,1850 5050,1850 5150,1850 4150,1950 4250,1950 4350,1950 4450,1950 4550,1950 4650,1950 4750,1950 4850,1950 4950,1950 5050,1950 5150,1950
ISENCE: C301.1 Q305.3 R310.1 R312.1 R315.2 R316.1 R317.2 R318.2 R319.2 | length 907.6
  Top Layer w15: v5(1940,4565) R312.1@2040,4565 2040,4595 2095,4650 R318.2@2095,4719.96 ; R315.2@2015,2619.96 2015,2565.83 2073.31,2507.52 R317.2@2073.31,2477.52 ; R316.1@2040,3500 2040,3530 2095,3585 R319.2@2095,3654.96 ; R318.2@2103.31,4719.96 R318.2@2103.31,4722.48 ; R310.1@2108.31,2172.56 2108.31,2228.31 2125,2245 2326.38,2245 Q305.3@2327.99,2243.39
  other v1: 2250,2200 2250,2300 2250,2400 2350,2400 2250,2500 2350,2500 1400,3350 1500,3350 1400,3450 1500,3450 1600,3450 1700,3450 1800,3450 1900,3450 1400,3550 1500,3550 1600,3550 1700,3550 1800,3550 1900,3550 1400,3650 1500,3650 1600,3650 1700,3650 1800,3650 1900,3650 2000,3650 1400,4400 1500,4400 1400,4500 1500,4500 1600,4500 1700,4500 1800,4500 1900,4500 1400,4600 1500,4600 1600,4600 1700,4600 1800,4600 1900,4600 1400,4700 1500,4700 1600,4700 1700,4700 1800,4700 1900,4700 2000,4700
  other v2: 2110,2720 1775,3565
IU: C302.1 Q303.3 R311.1 R312.2 R313.2 | length 448.9
  Top Layer w15: R311.1@2108.31,4262.56 2108.31,4317.52 2123.31,4332.52 Q303.3@2318.31,4332.52 ; R313.2@2195,4719.96 2195,4650 2250,4595 R312.2@2250,4565
  other v1: 2250,4300 2250,4400 2350,4400 2350,4500 2350,4600
IV: C300.1 Q304.3 R309.1 R314.2 R316.2 | length 458.4
  Top Layer w15: R309.1@2108.31,3202.56 2108.31,3256.21 2119.1,3267.01 Q304.3@2327.6,3267.01 2327.99,3267.01 Q304.3@2330,3265 ; R314.2@2195,3654.96 2195,3585 2250,3530 R316.2@2250,3500
  other v1: 2250,3250 2250,3350 2350,3400 2350,3500
M-NRST: C208.2 J200.5 R205.1 S200.1 U200.4 | length 2519.4
  Top Layer w15: J200.5@-30,4440.28 240.04,4440.28 S200.1@249.76,4450 249.76,4520.43 289.02,4559.69 R205.1@290,4559.69 C208.2@370,4559.68 ; v2(509.25,3260.75) U200.4@509.25,3330.63
  Bottom Layer w15: J200.5@-30,4440.28 -35.28,4435 -140,4435 -160,4415 -160,3269.53 -151.21,3260.75 v2(509.25,3260.75)
M-SWCLK: J200.4 U200.19 | length 1283.6
  Top Layer w15: U200.19@572.24,3659.37 v2(572.24,4340)
  Bottom Layer w15: J200.4@-30,4341.85 -28.15,4340 v2(572.24,4340)
M-SWDIO: J200.3 U200.18 | length 1217
  Top Layer w15: U200.18@603.74,3659.37 v2(603.74,4240)
  Bottom Layer w15: J200.3@-30,4243.42 -26.57,4240 v2(603.74,4240) v2@605,4240
MOTOR-A: C207.1 J101.5 Q300.3 Q303.2 R305.1 U200.24 | length 3134.4
  Top Layer w15: C207.1@19.84,3680 v2(19.84,3775) ; U200.24@414.76,3659.37 v2(414.76,3775) ; v2(1160,3775) 1160,3970 1185,3995 2454.44,3995 ; Q300.3@3439.02,4190.24 3444.25,4185 3649.52,4185 3658.31,4193.79 R305.1@3658.31,4252.48
  Bottom Layer w15: v2(19.84,3775) v2(414.76,3775) v2(1160,3775)
  other v1: 4750,2900 4850,2900 5050,2900 4650,3000 4750,3000 5050,3000 4650,3100 4750,3100 4850,3100 4950,3100 5050,3100 4550,3200 4650,3200 4750,3200 4850,3200 4950,3200 5050,3200 4350,3300 4450,3300 4550,3300 4650,3300 4350,3400 4450,3400 4550,3400 4650,3400 4350,3500 4450,3500 4550,3500 4650,3500 4350,3600 4450,3600 4550,3600 4650,3600 4350,3700 4450,3700 4550,3700 4650,3700 4350,3800 4450,3800 4550,3800 4650,3800 2450,3850 2550,3850 3450,3900 3550,3900 3650,3900 3750,3900 3850,3900 3950,3900 4050,3900 4150,3900 4250,3900 4350,3900 4450,3900 4550,3900 4650,3900 2450,3950 2550,3950 3450,4000 3550,4000 3650,4000 3750,4000 3850,4000 3950,4000 4050,4000 4150,4000 4250,4000 4350,4000 4450,4000 4550,4000 4650,4000 2450,4050 2550,4050 3450,4100 3550,4100 3650,4100 3750,4100 3850,4100 4350,4100 4450,4100 4550,4100 2450,4150 2550,4150 3550,4200 4450,4200 2550,4250 2450,4350 2550,4350 2450,4450 2550,4450
MOTOR-B: C206.1 J101.4 Q301.3 Q304.2 R303.1 U200.27 | length 4352.5
  Top Layer w15: C206.1@19.84,3495 19.84,3544.84 v2(20,3545) ; v2(240,3880) v2(240,3545) 357.87,3545 U200.27@360.63,3542.24 ; v2(1030,3880) 1030,2965 1050,2945 2455,2945 v1@2460,2950 ; 2445.13,2984.95 2445.13,3064.85 2485.08,3104.8 Q304.2@2485.08,3167.01 ; Q301.3@3439.8,3442.2 3442.01,3440 3649.52,3440 3658.31,3448.79 R303.1@3658.31,3507.48
  Bottom Layer w15: v2(20,3545) v2(240,3545) ; v2(240,3880) v2(1030,3880)
  other v1: 4350,2500 4450,2500 4550,2500 4650,2500 4750,2500 4900,2500 5050,2500 5150,2500 4350,2600 4450,2600 4550,2600 4650,2600 4750,2600 5050,2600 5150,2600 4350,2700 4450,2700 4550,2700 4650,2700 4750,2700 4850,2700 4950,2700 5050,2700 5150,2700 4250,2850 4350,2850 4450,2850 2475,2950 3450,2950 3550,2950 3650,2950 3750,2950 3850,2950 3950,2950 4050,2950 4150,2950 4250,2950 4350,2950 2555,2955 2475,3050 3450,3050 3550,3050 3650,3050 3750,3050 3850,3050 3950,3050 4050,3050 4150,3050 4250,3050 2555,3055 3450,3150 3550,3150 3650,3150 3750,3150 3850,3150 3950,3150 4050,3150 4150,3150 3450,3250 3550,3250 3650,3250 3750,3250 3850,3250 3950,3250 4050,3250 2475,3300 2555,3305 3450,3350 3550,3350 3650,3350 3750,3350 3850,3350 3950,3350 2475,3400 2555,3405 3550,3450 3450,3550 3550,3550
MOTOR-C: C205.1 J101.3 Q302.3 Q305.2 R304.1 U200.30 | length 4391.9
  Top Layer w15: v2(14.17,3355.75) 14.17,3315.79 C205.1@14.96,3315 ; v2(230,2310) 230,3435 242.76,3447.76 U200.30@360.63,3447.76 ; v2(1895,1905) 2450,1905 ; Q302.3@3439.8,2540.24 3638.54,2540.24 3658.31,2560 R304.1@3658.31,2599.96
  Bottom Layer w15: v2(14.17,3355.75) v2(230,3355.75) ; v2(230,2310) 720,2310 735,2295 735,1920 750,1905 v2(1895,1905)
  other v1: 2480,1950 2580,1950 3450,1950 3550,1950 3650,1950 3800,1950 2480,2050 2580,2050 3450,2050 3550,2050 3650,2050 3800,2050 3950,2100 4050,2100 4150,2100 4250,2100 4350,2100 4450,2100 4550,2100 4650,2100 4750,2100 4850,2100 4950,2100 5050,2100 5150,2100 2580,2150 3450,2150 3550,2150 3650,2150 3800,2150 3950,2200 4050,2200 4150,2200 4250,2200 4350,2200 4450,2200 4550,2200 4650,2200 4750,2200 5050,2200 5150,2200 2480,2250 2580,2250 3450,2250 3550,2250 3650,2250 3800,2250 3950,2300 4050,2300 4150,2300 4250,2300 4350,2300 4450,2300 4550,2300 4650,2300 4750,2300 5050,2300 5150,2300 2480,2350 2580,2350 3450,2350 3550,2350 3650,2350 3800,2350 3450,2450 3550,2500 3450,2600 3550,2600
NetC103_1: C103.1 R100.1 R103.2 U100.5 | length 414.1
  Top Layer w30: U100.5@605,917.11 726.75,917.11 739.65,930 782.43,930 800,912.43 800,877.57 812.26,865.31 855.47,865.31 R100.1@863.31,857.48 C103.1@963.31,857.48
NetC104_2: C104.2 C105.2 R105.2 VR100.3 | length 354.3
  Top Layer w30: R105.2@93.66,1430 93.66,1443.19 86.42,1450.43 75.37,1450.43 57.8,1468.01 C104.2@57.8,1523.31 C105.2@57.8,1598.31 107.43,1598.31 125,1615.88 125,1703.23 VR100.3@123.03,1705.2
NetC109_1: C109.1 D100.1 L100.1 U100.1 | length 513.9
  Top Layer w30: L100.1@175,815 175,722.53 192.57,704.96 C109.1@300,704.96 C109.1@301.03,703.93 ; D100.1@303.99,571.83 301.99,573.83 301.99,702.97 C109.1@301.03,703.93 ; U100.1@455,702.89 453.97,703.93 C109.1@301.03,703.93
NetC109_2: C109.2 R102.1 | length 79.9
  Top Layer w30: C109.2@300,775.04 R102.1@300,854.96
NetC110_1: C110.1 C111.2 C112.2 L101.2 R104.2 U100.3 | length 1643.3
  Top Layer w30: U100.3@555,702.89 555,581.3 560.32,575.98 R104.2@560.32,575 695.47,575 706.81,586.34 C112.2@720,586.34 C111.2@840,586.34 840,457.57 822.43,440 452.57,440 435,422.43 435,215 470.01,179.99 482.8,167.2 C110.1@595,167.2 811.73,167.2 845,200.47 L101.2@845,230
NetC116_2: C116.2 C117.2 R109.2 VR101.3 | length 340.3
  Top Layer w30: R109.2@488.66,1430 488.66,1443.19 481.42,1450.43 472.89,1450.43 455.32,1468.01 C116.2@455.32,1523.31 C117.2@455.32,1598.31 497.43,1598.31 515,1615.88 515,1701.34 VR101.3@515.55,1701.89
